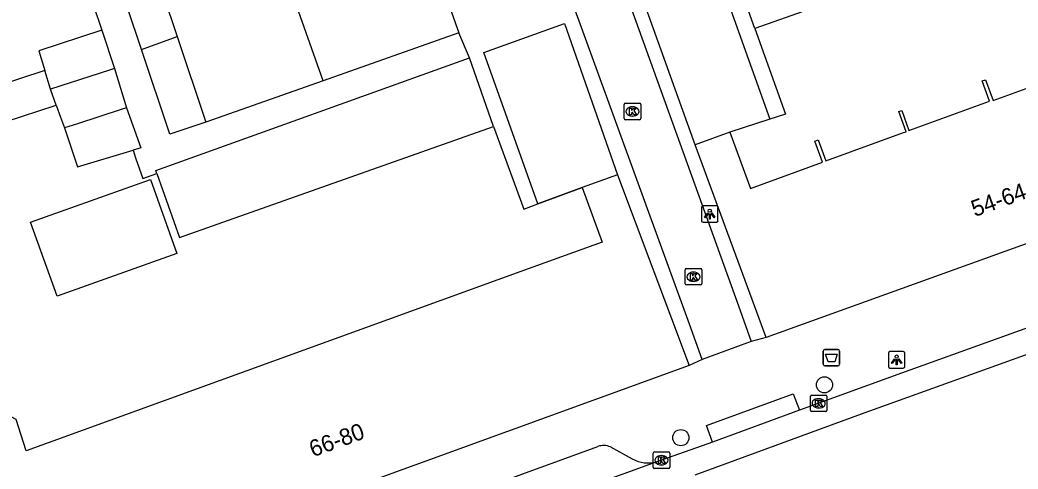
# Model space of a CAD drawing. Extents: x 159377 to 159983, y 382996 to 383595.
# Drawn here: x 159669.3 to 159729.8, y 383125.8 to 383153 of the extents above; entities that cross this region are included whole.
import ezdxf

# ---------------------------------------------------------------- set-up
doc = ezdxf.new("R2010")
doc.units = 0
for name, color, linetype in [('IMGEO_Afvalbak', 7, 'Continuous'), ('IMGEO_Boom', 7, 'Continuous'), ('IMGEO_Kolk', 7, 'Continuous'), ('IMGEO_Lichtpunt', 7, 'Continuous'), ('IMGEO_Muur', 7, 'Continuous'), ('IMGEO_Pand', 7, 'Continuous'), ('IMGEO_Pand_nummerreeks', 7, 'Continuous'), ('IMGEO_Parkeervlak_open', 7, 'Continuous'), ('IMGEO_Rijbaan_lokaal_gesloten', 7, 'Continuous'), ('IMGEO_Rijbaan_lokaal_open', 7, 'Continuous'), ('IMGEO_Voetpad_open', 7, 'Continuous')]:
    doc.layers.add(name, color=color, linetype=linetype)

msp = doc.modelspace()

# ---------------------------------------------------------------- linework, layer by layer
at = {"layer": 'IMGEO_Afvalbak'}
for p, q in [((159717.966, 383132.184), (159717.966, 383132.984)), ((159717.966, 383132.984), (159717.966, 383132.184)), ((159718.066, 383133.084), (159718.856, 383133.084)), ((159718.856, 383133.084), (159718.066, 383133.084)), ((159718.956, 383132.984), (159718.956, 383132.184)), ((159718.956, 383132.184), (159718.956, 383132.984)), ((159718.856, 383132.084), (159718.066, 383132.084)), ((159718.066, 383132.084), (159718.856, 383132.084))]:
    msp.add_line(p, q, dxfattribs=at)
msp.add_lwpolyline([(159718.109, 383132.798), (159718.813, 383132.798), (159718.664, 383132.328), (159718.258, 383132.328), (159718.109, 383132.798)], dxfattribs=at)
for centre, start, end in [((159718.066, 383132.984), 90, 180), ((159718.066, 383132.984), 90, 180), ((159718.856, 383132.984), 0, 90), ((159718.856, 383132.984), 360, 90), ((159718.066, 383132.184), 180, 270), ((159718.066, 383132.184), 180, 270), ((159718.856, 383132.184), 270, 0), ((159718.856, 383132.184), 270, 0)]:
    msp.add_arc(centre, 0.1, start, end, dxfattribs=at)
at = {"layer": 'IMGEO_Boom'}
for centre in [(159718.038, 383130.938), (159709.344, 383127.737)]:
    msp.add_circle(centre, 0.489, dxfattribs=at)
at = {"layer": 'IMGEO_Kolk'}
for p, q in [((159705.915, 383147.074), (159705.915, 383147.926)), ((159705.99, 383148), (159706.842, 383148)), ((159706.916, 383147.926), (159706.916, 383147.074)), ((159706.426, 383147.22), (159706.401, 383147.22)), ((159706.403, 383147.78), (159706.428, 383147.78)), ((159706.842, 383147), (159705.99, 383147)), ((159709.605, 383137.061), (159709.605, 383137.913)), ((159709.68, 383137.987), (159710.532, 383137.987)), ((159710.093, 383137.767), (159710.118, 383137.767)), ((159710.606, 383137.913), (159710.606, 383137.061)), ((159710.532, 383136.987), (159709.68, 383136.987)), ((159710.116, 383137.207), (159710.091, 383137.207)), ((159717.259, 383130.317), (159718.111, 383130.317)), ((159717.184, 383129.391), (159717.184, 383130.243)), ((159717.672, 383130.097), (159717.697, 383130.097)), ((159718.185, 383130.243), (159718.185, 383129.391)), ((159718.111, 383129.317), (159717.259, 383129.317)), ((159717.695, 383129.537), (159717.67, 383129.537)), ((159707.668, 383125.944), (159707.668, 383126.796)), ((159707.743, 383126.87), (159708.595, 383126.87)), ((159708.156, 383126.65), (159708.181, 383126.65)), ((159708.669, 383126.796), (159708.669, 383125.944)), ((159708.179, 383126.09), (159708.154, 383126.09)), ((159708.595, 383125.87), (159707.743, 383125.87))]:
    msp.add_line(p, q, dxfattribs=at)
for points in [[(159705.915, 383147.074), (159705.915, 383147.926)], [(159705.99, 383148), (159706.842, 383148)], [(159706.916, 383147.926), (159706.916, 383147.074)], [(159706.236, 383147.7), (159706.359, 383147.7), (159706.359, 383147.549), (159706.489, 383147.7), (159706.653, 383147.7), (159706.507, 383147.549), (159706.66, 383147.3), (159706.508, 383147.3), (159706.423, 383147.464), (159706.359, 383147.397), (159706.359, 383147.3), (159706.236, 383147.3), (159706.236, 383147.7)], [(159706.842, 383147), (159705.99, 383147)], [(159709.605, 383137.061), (159709.605, 383137.913)], [(159709.68, 383137.987), (159710.532, 383137.987)], [(159709.926, 383137.687), (159710.049, 383137.687), (159710.049, 383137.536), (159710.179, 383137.687), (159710.343, 383137.687), (159710.197, 383137.536), (159710.35, 383137.287), (159710.198, 383137.287), (159710.113, 383137.451), (159710.049, 383137.384), (159710.049, 383137.287), (159709.926, 383137.287), (159709.926, 383137.687)], [(159710.606, 383137.913), (159710.606, 383137.061)], [(159710.532, 383136.987), (159709.68, 383136.987)], [(159717.259, 383130.317), (159718.111, 383130.317)], [(159717.184, 383129.391), (159717.184, 383130.243)], [(159717.505, 383130.017), (159717.628, 383130.017), (159717.628, 383129.866), (159717.758, 383130.017), (159717.922, 383130.017), (159717.776, 383129.866), (159717.929, 383129.617), (159717.777, 383129.617), (159717.692, 383129.781), (159717.628, 383129.714), (159717.628, 383129.617), (159717.505, 383129.617), (159717.505, 383130.017)], [(159718.185, 383130.243), (159718.185, 383129.391)], [(159718.111, 383129.317), (159717.259, 383129.317)], [(159707.668, 383125.944), (159707.668, 383126.796)], [(159707.743, 383126.87), (159708.595, 383126.87)], [(159708.669, 383126.796), (159708.669, 383125.944)], [(159707.989, 383126.57), (159708.112, 383126.57), (159708.112, 383126.419), (159708.242, 383126.57), (159708.406, 383126.57), (159708.26, 383126.419), (159708.413, 383126.17), (159708.261, 383126.17), (159708.176, 383126.334), (159708.112, 383126.267), (159708.112, 383126.17), (159707.989, 383126.17), (159707.989, 383126.57)], [(159708.595, 383125.87), (159707.743, 383125.87)]]:
    msp.add_lwpolyline(points, dxfattribs=at)
for centre, start, end in [((159705.992, 383147.924), 91.55205, 178.44795), ((159705.992, 383147.924), 91.55205, 178.44795), ((159706.84, 383147.924), 1.55205, 88.44795), ((159706.84, 383147.924), 1.55205, 88.44795), ((159705.992, 383147.076), 181.55205, 268.44795), ((159705.992, 383147.076), 181.55205, 268.44795), ((159706.84, 383147.076), 271.55205, 358.44795), ((159706.84, 383147.076), 271.55205, 358.44795), ((159709.682, 383137.911), 91.55205, 178.44795), ((159709.682, 383137.911), 91.55205, 178.44795), ((159710.53, 383137.911), 1.55205, 88.44795), ((159710.53, 383137.911), 1.55205, 88.44795), ((159709.682, 383137.063), 181.55205, 268.44795), ((159709.682, 383137.063), 181.55205, 268.44795), ((159710.53, 383137.063), 271.55205, 358.44795), ((159710.53, 383137.063), 271.55205, 358.44795), ((159717.261, 383130.241), 91.55205, 178.44795), ((159717.261, 383130.241), 91.55205, 178.44795), ((159718.109, 383130.241), 1.55205, 88.44795), ((159718.109, 383130.241), 1.55205, 88.44795), ((159717.261, 383129.393), 181.55205, 268.44795), ((159717.261, 383129.393), 181.55205, 268.44795), ((159718.109, 383129.393), 271.55205, 358.44795), ((159718.109, 383129.393), 271.55205, 358.44795), ((159707.745, 383126.794), 91.55205, 178.44795), ((159707.745, 383126.794), 91.55205, 178.44795), ((159708.593, 383126.794), 1.55205, 88.44795), ((159708.593, 383126.794), 1.55205, 88.44795), ((159707.745, 383125.946), 181.55205, 268.44795), ((159707.745, 383125.946), 181.55205, 268.44795), ((159708.593, 383125.946), 271.55205, 358.44795), ((159708.593, 383125.946), 271.55205, 358.44795)]:
    msp.add_arc(centre, 0.0765, start, end, dxfattribs=at)
for centre, major_axis, ratio, start_param, end_param in [((159706.402, 383147.5), (-0.387, 0.002), 0.722429, 4.712389, 7.853982), ((159706.427, 383147.5), (-0.39, 0.002), 0.717154, 1.570796, 4.712389), ((159710.092, 383137.487), (-0.387, 0.002), 0.722429, 4.712389, 7.853982), ((159710.117, 383137.487), (-0.39, 0.002), 0.717154, 1.570796, 4.712389), ((159717.671, 383129.817), (-0.387, 0.002), 0.722429, 4.712389, 7.853982), ((159717.696, 383129.817), (-0.39, 0.002), 0.717154, 1.570796, 4.712389), ((159708.155, 383126.37), (-0.387, 0.002), 0.722429, 4.712389, 7.853982), ((159708.18, 383126.37), (-0.39, 0.002), 0.717154, 1.570796, 4.712389)]:
    msp.add_ellipse(centre, major_axis=major_axis, ratio=ratio, start_param=start_param, end_param=end_param, dxfattribs=at)
at = {"layer": 'IMGEO_Lichtpunt'}
for p, q in [((159711.499, 383141.784), (159710.691, 383141.784)), ((159711.499, 383141.784), (159710.691, 383141.784)), ((159710.597, 383141.689), (159710.597, 383140.882)), ((159710.597, 383141.689), (159710.597, 383140.882)), ((159711.593, 383140.882), (159711.593, 383141.689)), ((159711.593, 383140.882), (159711.593, 383141.689)), ((159710.691, 383140.788), (159711.499, 383140.788)), ((159710.691, 383140.788), (159711.499, 383140.788)), ((159721.91, 383132.853), (159721.91, 383132.046)), ((159721.91, 383132.853), (159721.91, 383132.046)), ((159722.812, 383132.948), (159722.004, 383132.948)), ((159722.812, 383132.948), (159722.004, 383132.948)), ((159722.906, 383132.046), (159722.906, 383132.853)), ((159722.906, 383132.046), (159722.906, 383132.853)), ((159722.004, 383131.952), (159722.812, 383131.952)), ((159722.004, 383131.952), (159722.812, 383131.952))]:
    msp.add_line(p, q, dxfattribs=at)
for points in [[(159710.971, 383141.353), (159711.01, 383141.325), (159710.822, 383141.063), (159710.784, 383141.09), (159710.971, 383141.353)], [(159711.073, 383141.305), (159711.12, 383141.305), (159711.12, 383140.983), (159711.073, 383140.983), (159711.073, 383141.305)], [(159711.183, 383141.325), (159711.221, 383141.352), (159711.408, 383141.09), (159711.369, 383141.062), (159711.183, 383141.325)], [(159722.284, 383132.517), (159722.323, 383132.489), (159722.135, 383132.227), (159722.097, 383132.254), (159722.284, 383132.517)], [(159722.386, 383132.469), (159722.433, 383132.469), (159722.433, 383132.147), (159722.386, 383132.147), (159722.386, 383132.469)], [(159722.496, 383132.489), (159722.534, 383132.516), (159722.721, 383132.254), (159722.682, 383132.226), (159722.496, 383132.489)]]:
    msp.add_lwpolyline(points, dxfattribs=at)
for centre in [(159711.096, 383141.487), (159722.409, 383132.651)]:
    msp.add_circle(centre, 0.0994, dxfattribs=at)
for centre, start, end in [((159710.691, 383141.689), 90, 180), ((159710.691, 383141.689), 90, 180), ((159711.499, 383141.689), 0, 90), ((159711.499, 383141.689), 0, 90), ((159710.691, 383140.882), 180, 270), ((159710.691, 383140.882), 180, 270), ((159711.499, 383140.882), 270, 0), ((159711.499, 383140.882), 270, 360), ((159722.004, 383132.853), 90, 180), ((159722.004, 383132.853), 90, 180), ((159722.812, 383132.853), 0, 90), ((159722.812, 383132.853), 0, 90), ((159722.004, 383132.046), 180, 270), ((159722.004, 383132.046), 180, 270), ((159722.812, 383132.046), 270, 0), ((159722.812, 383132.046), 270, 360)]:
    msp.add_arc(centre, 0.0946, start, end, dxfattribs=at)
at = {"layer": 'IMGEO_Muur'}
for points in [[(159713.814, 383152.518), (159715.68, 383147.331), (159714.733, 383147.026)], [(159698.005, 383146.592), (159699.831, 383141.577), (159700.696, 383141.898)], [(159714.733, 383147.026), (159712.317, 383146.247)], [(159700.696, 383141.898), (159703.379, 383142.892)]]:
    msp.add_lwpolyline(points, dxfattribs=at)
at = {"layer": 'IMGEO_Pand'}
for points in [[(159722.387, 383160.075), (159723.81, 383156.058), (159713.814, 383152.518)], [(159694.04, 383157.513), (159695.898, 383152.266)], [(159677.142, 383157.163), (159678.86, 383152.034)], [(159676.698, 383151.254), (159674.98, 383156.383)], [(159713.814, 383152.518), (159712.391, 383156.535)], [(159687.69, 383149.36), (159685.85, 383154.557)], [(159674.295, 383152.417), (159670.484, 383151.179), (159670.844, 383149.972)], [(159674.295, 383152.417), (159675.06, 383150.104)], [(159676.698, 383151.254), (159678.86, 383152.034)], [(159678.86, 383152.034), (159680.595, 383146.854)], [(159695.898, 383152.266), (159687.69, 383149.36)], [(159747.127, 383151.995), (159745.927, 383151.539), (159747.314, 383147.733), (159747.149, 383147.673), (159747.032, 383147.994), (159745.882, 383147.587), (159746.655, 383145.405), (159714.513, 383133.801)], [(159680.595, 383146.854), (159678.417, 383146.124), (159676.698, 383151.254)], [(159677.618, 383143.736), (159677.552, 383143.921), (159696.555, 383150.754)], [(159698.005, 383146.592), (159696.555, 383150.754)], [(159670.844, 383149.972), (159667.817, 383148.988), (159668.449, 383146.867), (159671.534, 383147.871)], [(159671.18, 383148.844), (159670.844, 383149.972)], [(159675.06, 383150.104), (159674.748, 383150.003), (159671.18, 383148.844)], [(159675.06, 383150.104), (159675.793, 383147.717)], [(159712.317, 383146.247), (159713.552, 383142.838), (159717.926, 383144.423), (159717.463, 383145.703), (159717.664, 383145.776), (159718.122, 383144.511), (159722.824, 383146.214), (159722.976, 383146.269), (159722.535, 383147.486), (159722.718, 383147.552), (159723.154, 383146.348), (159728.03, 383148.115), (159727.585, 383149.346), (159727.793, 383149.421), (159728.249, 383148.161), (159733.129, 383149.929)], [(159671.534, 383147.871), (159671.18, 383148.844)], [(159671.534, 383147.871), (159671.796, 383147.16), (159672.033, 383146.496)], [(159675.793, 383147.717), (159675.462, 383147.609), (159672.818, 383146.751), (159672.033, 383146.496)], [(159675.793, 383147.717), (159676.653, 383145.288), (159676.528, 383145.25), (159676.195, 383145.151)], [(159677.618, 383143.736), (159678.991, 383139.86), (159698.005, 383146.592)], [(159672.033, 383146.496), (159672.812, 383144.142), (159676.195, 383145.151)], [(159712.317, 383146.247), (159710.207, 383145.482)], [(159714.513, 383133.801), (159710.207, 383145.482)], [(159705.514, 383143.666), (159703.379, 383142.892)], [(159705.514, 383143.666), (159709.84, 383132.115)], [(159677.235, 383143.385), (159678.838, 383138.891), (159671.585, 383136.304), (159669.982, 383140.798), (159677.235, 383143.385)], [(159703.379, 383142.892), (159704.579, 383139.579), (159699.879, 383137.876), (159669.71, 383126.945), (159669.098, 383128.842), (159668.061, 383129.373), (159666.005, 383128.71)], [(159709.84, 383132.115), (159671.247, 383118.076)]]:
    msp.add_lwpolyline(points, dxfattribs=at)
at = {"layer": 'IMGEO_Parkeervlak_open'}
for points in [[(159714.733, 383147.026), (159712.317, 383146.247)], [(159703.379, 383142.892), (159700.696, 383141.898)]]:
    msp.add_lwpolyline(points, dxfattribs=at)
at = {"layer": 'IMGEO_Rijbaan_lokaal_gesloten'}
for points in [[(159754.536, 383141.637), (159750.483, 383140.138), (159744.149, 383137.754), (159720.256, 383129.159), (159710.189, 383125.473)], [(159734.999, 383136.062), (159722.708, 383131.636), (159716.523, 383129.402)], [(159716.523, 383129.402), (159711.254, 383127.474)], [(159711.254, 383127.474), (159707.898, 383126.277)], [(159707.898, 383126.277), (159690.763, 383120.054), (159685.995, 383118.056), (159684.873, 383117.488), (159679.87, 383114.377), (159667.189, 383106.051)]]:
    msp.add_lwpolyline(points, dxfattribs=at)
at = {"layer": 'IMGEO_Rijbaan_lokaal_open'}
for points in [[(159698.578, 383176.847), (159698.668, 383176.596), (159698.957, 383176.699), (159705.773, 383157.67), (159705.026, 383157.403), (159712.83, 383135.72), (159713.607, 383133.562)], [(159710.636, 383132.475), (159709.858, 383134.615), (159702.376, 383155.2), (159700.541, 383154.623), (159693.435, 383174.689), (159693.704, 383174.782), (159693.603, 383175.063)], [(159713.607, 383133.562), (159710.636, 383132.475)]]:
    msp.add_lwpolyline(points, dxfattribs=at)
at = {"layer": 'IMGEO_Voetpad_open'}
for points in [[(159710.207, 383145.482), (159706.935, 383154.603), (159711.457, 383156.204), (159714.733, 383147.026)], [(159673.283, 383155.434), (159674.295, 383152.417)], [(159700.696, 383141.898), (159697.424, 383151.066), (159702.301, 383152.82), (159705.514, 383143.666)], [(159696.555, 383150.754), (159695.898, 383152.266)], [(159713.814, 383152.518), (159715.68, 383147.331), (159714.733, 383147.026)], [(159687.69, 383149.36), (159680.595, 383146.854)], [(159698.005, 383146.592), (159699.831, 383141.577), (159700.696, 383141.898)], [(159676.195, 383145.151), (159676.335, 383144.683), (159676.779, 383143.437), (159677.618, 383143.736)], [(159714.513, 383133.801), (159713.607, 383133.562)], [(159710.636, 383132.475), (159709.84, 383132.115)], [(159711.254, 383127.474), (159710.896, 383128.481), (159716.134, 383130.396), (159716.523, 383129.402)], [(159668.701, 383109.56), (159678.752, 383116.143), (159683.842, 383119.278), (159685.613, 383120.175), (159690.25, 383122.082), (159704.322, 383127.204)], [(159705.079, 383127.175), (159706.403, 383126.45)]]:
    msp.add_lwpolyline(points, dxfattribs=at)
for centre, radius, start, end in [((159704.664, 383126.238), 1.025, 66.12239, 109.48986), ((159707.364, 383128.211), 2.007, 241.37518, 285.42311)]:
    msp.add_arc(centre, radius, start, end, dxfattribs=at)

# ---------------------------------------------------------------- texts
at = {"layer": 'IMGEO_Pand_nummerreeks'}
for s, rotation, p in [('54-64', 19.86445, (159727.137, 383141.098)), ('66-80', 20.02665, (159687.073, 383126.546))]:
    msp.add_text(s, height=1, rotation=rotation, dxfattribs=at).set_placement(p)

doc.saveas('drawing.dxf')
